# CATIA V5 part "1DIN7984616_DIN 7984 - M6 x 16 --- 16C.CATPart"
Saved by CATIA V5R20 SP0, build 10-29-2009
Part number: 1DIN7984616_DIN 7984 - M6 x 16 --- 16C
Revision: ANY
Definition: UNKNOWN
Nomenclature: 1DIN7984616_DIN 7984 - M6 x 16 --- 16C
Source: Unknown
Bounding box of the stored display mesh (mm): x 0 to 20, y -5 to 5, z -5 to 5
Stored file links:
  C:\Users\Utente\Desktop\IO LAVORO\3D X SITO CF\CUMSA\3D files PW\pw101630\pw101630_ejection\1DIN7984616_DIN 7984 - M6 x 16 --- 16C.CATPart
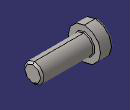
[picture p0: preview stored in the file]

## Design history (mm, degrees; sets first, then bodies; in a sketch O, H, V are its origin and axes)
Body1 "Hex" (main body)
  Solid1: solid without history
